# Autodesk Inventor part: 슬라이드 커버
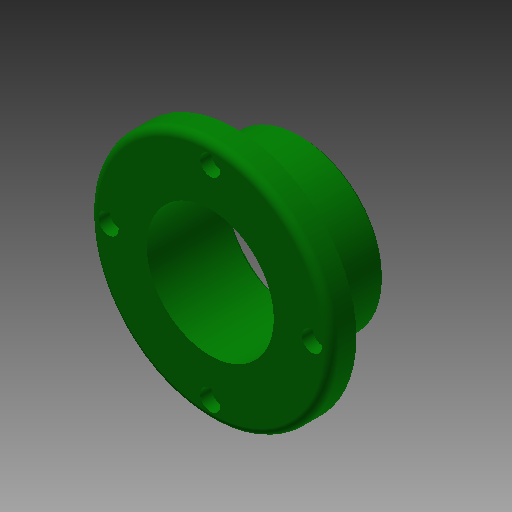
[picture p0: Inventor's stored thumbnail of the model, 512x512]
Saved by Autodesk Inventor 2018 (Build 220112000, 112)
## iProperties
Created: 2015-10
Part Number: 슬라이드 커버
Document SubType Name: Modeling
Designer: mdu
Density: 7.86 g/cm^3
Material: 알루미늄 6061
Mass: 598.523 g
Surface Area: 229.996 cm^2
Volume: 76.148 cm^3
Appearance: 진녹색
Author: mdu
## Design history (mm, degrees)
sketch "스케치1"
  geometry: C1 r 47.5 at (0, 0); C2 r 32.5 at (0, 0); 1 further point
  constraints: 2 centre point, 2 coincident
  dimensions: "d33" = 95 diameter of C1; "d35" = 65 diameter of C2
extrude "돌출1" new body sketch "스케치1" distance "d0" = 10; taper "d1" = 0 deg
extrude "돌출2" join sketch "스케치1" distance "d2" = 26; taper "d3" = 0 deg
hole "구멍1" diameter "d6" = 50; stored, may be unused: countersink angle "d10" = 90 deg, drill point angle "d12" = 118 deg; dims "d4" = 10, "d5" = 10, "d7" = 6, "d8" = 4, "d9" = 2, "d11" = 8
sketch "스케치2" dims "d36" = 80
  geometry: 4 further points
  constraints: 2 coincident, 2 vertical alignment, 2 other
hole "구멍2" sketch "스케치2" at (0, 40) diameter "d13" = 4.5; stored, may be unused: countersink angle "d17" = 90 deg, drill point angle "d19" = 118 deg; dims "d14" = 6, "d15" = 8, "d16" = 4.4, "d18" = 8
fillet "모깎기1" dims "d23" = 3
chamfer "모따기1" distance "d24" = 1; stored, may be unused: second distance "d25" = 2, angle "d26" = 45 deg
sketch "스케치3"
  geometry: C1 r 25 at (0, 0); C2 r 30 at (0, 0); C3 r 26 at (0, 0) reference; 1 further point
  constraints: 2 centre point, 2 coincident
  dimensions: "d27" = 60 diameter of C2
extrude "돌출3" cut sketch "스케치3" distance "d28" = 3; taper "d29" = 0 deg
chamfer "모따기2" distance "d30" = 1; stored, may be unused: second distance "d31" = 2, angle "d32" = 45 deg
node "솔리드1"
pattern_circular "원형 패턴1" dims angle "d21" = 360 deg
